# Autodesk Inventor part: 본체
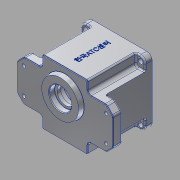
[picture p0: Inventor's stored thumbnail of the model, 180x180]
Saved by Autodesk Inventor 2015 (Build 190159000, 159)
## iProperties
Created: 2016-02
Part Number: 본체
Material: Aluminum 6061
Document SubType Name: Modeling
Designer: Administrator
Mass: 878.532 g
Surface Area: 762.372 cm^2
Volume: 325.382 cm^3
Density: 2.7 g/cm^3
Appearance: Aluminum - Flat
Author: Administrator
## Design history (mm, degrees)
sketch "Sketch1"
  geometry: L1 (70, 30)-(-70, 30); L2 (-70, 30)-(-70, -30); L3 (-70, -30)-(70, -30); L4 (70, -30)-(70, 30); L5 (70, 30)-(-70, -30); L6 (-70, 30)-(70, -30); 1 further point
  constraints: 12 end point, 2 midpoint, 2 parallel, 1 horizontal, 1 perpendicular
  dimensions: "d0" = 140 distance of L3.end L2.end; "d1" = 60 distance of L2.end L1.end
extrude "Extrusion1" new body sketch "Sketch1" distance "d2" = 13; taper "d3" = 0 deg
sketch "Sketch2"
  geometry: L1 (-47, 47)-(47, 47); L2 (47, 47)-(47, -47); L3 (47, -47)-(-47, -47); L4 (-47, -47)-(-47, 47); L5 (-47, 47)-(47, -47); L6 (47, 47)-(-47, -47); 1 further point
  constraints: 12 end point, 2 midpoint, 2 parallel, 1 horizontal, 1 perpendicular
  dimensions: "d4" = 94 distance of L2.end L3.end; "d5" = 94 distance of L1.end L2.end
extrude "Extrusion2" join sketch "Sketch2" distance "d6" = 80; taper "d7" = 0 deg
sketch "Sketch3"
  geometry: C1 r 43 at (0, 0); 1 further point
  constraints: 1 centre point, 1 coincident
  dimensions: "d8" = 86 diameter of C1
extrude "Extrusion3" cut sketch "Sketch3" distance "d9" = 9; taper "d10" = 0 deg
sketch "Sketch4"
  geometry: A1 r 40 centre (0, 0) between (-39.148, 8.214) and (-39.148, -8.214); A2 r 36 centre (0, 0) between (36, 0) and (-36, 0); A3 r 4 centre (36, 0) between (35.854, 3.997) and (35.852, -3.997); A4 r 4 centre (-36, 0) between (-35.852, -3.997) and (-35.852, 3.997); A5 r 3.5 centre (35.722, -7.495) between (39.148, -8.214) and (35.852, -3.997); A6 r 3.5 centre (-35.722, -7.495) between (-35.852, -3.997) and (-39.148, -8.214); A7 r 3.5 centre (-35.722, 7.495) between (-39.148, 8.214) and (-35.852, 3.997); A8 r 3.5 centre (35.722, 7.495) between (35.852, 3.997) and (39.148, 8.214); 1 further point
  constraints: 19 point on circle, 8 centre point, 8 tangent, 4 equal radius, 2 coincident, 2 horizontal alignment
  dimensions: "d11" = 80 diameter of A1; "d12" = 72 diameter of A2; "d13" = 4 radius of A3; "d14" = 3.5 radius of A5
extrude "Extrusion4" cut sketch "Sketch4" distance "d15" = 62; taper "d16" = 0 deg
sketch "Sketch5"
  geometry: C1 r 21 at (0, -11); C2 r 15 at (0, 20); 1 further point
  constraints: 2 centre point, 2 vertical alignment
  dimensions: "d17" = 42 diameter of C1; "d18" = 30 diameter of C2; "d19" = 11 distance of C1.centre point (0, 0); "d20" = 20 distance of point (0, 0) C2.centre
extrude "Extrusion5" join sketch "Sketch5" distance "d21" = 7; taper "d22" = 0 deg
hole "Hole1" diameter "d25" = 25; stored, may be unused: countersink angle "d29" = 90 deg, drill point angle "d31" = 0 deg; dims "d26" = 6, "d27" = 35, "d28" = 10, "d30" = 15, "d118" = 10, "d119" = 10
sketch "Sketch6"
  geometry: C1 r 28 at (0, 11); 1 further point
  constraints: 1 centre point, 1 vertical alignment
  dimensions: "d32" = 56 diameter of C1; "d33" = 11 distance of C1.centre point (0, 0)
extrude "Extrusion6" join sketch "Sketch6" distance "d34" = 7; taper "d35" = -10 deg
hole "Hole2" diameter "d38" = 25; stored, may be unused: countersink angle "d42" = 90 deg, drill point angle "d44" = 0 deg; dims "d36" = 10, "d37" = 10, "d39" = 6, "d40" = 32, "d41" = 8, "d43" = 13
hole "Hole3" diameter "d47" = 19; stored, may be unused: countersink angle "d51" = 90 deg, drill point angle "d53" = 0 deg; dims "d45" = 10, "d46" = 10, "d48" = 6, "d49" = 22, "d50" = 7, "d52" = 8
chamfer "Chamfer1" distance "d54" = 10; stored, may be unused: second distance "d55" = 2, angle "d56" = 45 deg
sketch "Sketch8"
  geometry: 3 further points
  constraints: 1 vertical alignment
  dimensions: "d57" = 38 distance of point (-60, -19) point (-60, 19); "d58" = 19 vertical distance of point (-60, -19) point (0, 0); "d59" = 60 horizontal distance of point (0, 0) point (-60, 19)
hole "Hole4" sketch "Sketch8" at (-60, 19), (-60, -19) diameter "d60" = 5; stored, may be unused: countersink angle "d64" = 90 deg, drill point angle "d66" = 0 deg; dims "d61" = 6, "d62" = 22, "d63" = 7, "d65" = 9
sketch "Sketch9"
  geometry: C1 r 2.5 at (-60, -19) reference; C2 r 2.5 at (-60, 19) reference; 1 further point
hole "Hole5" sketch "Sketch9" at (-60, -19), (-60, 19) diameter "d67" = 9; stored, may be unused: countersink angle "d71" = 90 deg, drill point angle "d73" = 0 deg; dims "d68" = 6, "d69" = 22, "d70" = 7, "d72" = 4
mirror "Mirror1"
sketch "Sketch10"
  geometry: L1 (-47, 47)-(47, 47) reference; L2 (47, 47)-(47, 30) reference; L3 (33, 47)-(47, 47); L4 (47, 47)-(47, 30); L5 (47, 30)-(33, 30); L6 (33, 30)-(33, 47); L7 (33, 47)-(47, 30); L8 (47, 47)-(33, 30); 2 further points
  constraints: 12 end point, 2 midpoint, 2 parallel, 1 horizontal, 1 perpendicular
  dimensions: "d74" = 14 distance of L4.end L5.end; "d75" = 17 distance of L1.end L4.end
extrude "Extrusion7" cut sketch "Sketch10" distance "d76" = 70; taper "d77" = 0 deg
mirror "Mirror2"
mirror "Mirror3"
fillet "Fillet1" dims "d78" = 8
sketch "Sketch12"
  geometry: 3 further points
  constraints: 1 horizontal alignment
  dimensions: "d79" = 40 horizontal distance of point (-33, 30) point (7, 70); "d80" = 80 distance of point (7, 70) point (-73, 70); "d81" = 40 horizontal distance of point (7, 70) point (-33, 30)
hole "Hole6" sketch "Sketch12" at (-73, 70), (7, 70) diameter "d82" = 7; stored, may be unused: countersink angle "d86" = 90 deg, drill point angle "d88" = 0 deg; dims "d83" = 6, "d84" = 22, "d85" = 7, "d87" = 4
mirror "Mirror4"
sketch "Sketch13"
  geometry: A1 r 4 centre (36, 0) between (35.852, 3.997) and (35.852, -3.997) reference; A2 r 4 centre (-36, 0) between (-35.852, -3.997) and (-35.852, 3.997) reference; 1 further point
hole "Hole7" sketch "Sketch13" at (36, 0), (-36, 0) diameter "d89" = 3.242; stored, may be unused: countersink angle "d93" = 90 deg, drill point angle "d95" = 118 deg; dims "d90" = 7, "d91" = 22, "d92" = 7, "d94" = 9
fillet "Fillet2" dims "d97" = 5
sketch "Sketch16" dims "d9" = 9, "d10" = 0
  geometry: L1 (-66, 0)-(0, 0) reference; L2 (-72, 80)-(6, 80) reference; 3 further points
  constraints: 1 midpoint, 1 vertical alignment, 1 other
  dimensions: "d98" = 40 distance from line of L2 point (-33, 40)
emboss "Emboss1" sketch "Sketch16" dims "d9" = 9, "d10" = 0, "d99" = 0.5, "d100" = 0
chamfer "Chamfer2" distance "d101" = 1; stored, may be unused: second distance "d102" = 2, angle "d103" = 45 deg
fillet "Fillet3" dims "d104" = 0.3
fillet "Fillet4" dims "d105" = 5
fillet "Fillet6" dims "d107" = 3
fillet "Fillet7" dims "d108" = 2
fillet "Fillet8" dims "d109" = 2
fillet "Fillet9" dims "d110" = 2
sketch "Sketch17"
  geometry: L1 (-33, 47)-(-33, 35) reference; L2 (-57.929, 30)-(-38, 30) reference; L3 (-68.536, 21.464)-(-61.464, 28.536) reference; L4 (-70, -17.929)-(-70, 17.929) reference; L5 (-61.464, -28.536)-(-68.536, -21.464) reference; L6 (-38, -30)-(-57.929, -30) reference; L7 (-33, -35)-(-33, -47) reference; L8 (33, -47)-(-33, -47) reference; L9 (33, -47)-(33, -35) reference; L10 (57.929, -30)-(38, -30) reference; L11 (68.536, -21.464)-(61.464, -28.536) reference; L12 (70, 17.929)-(70, -17.929) reference; L13 (61.464, 28.536)-(68.536, 21.464) reference; L14 (38, 30)-(57.929, 30) reference; L15 (33, 35)-(33, 47) reference; L16 (-33, 47)-(33, 47) reference; L17 (32, 45)-(32, 35); L18 (38, 29)-(57.929, 29); L19 (60.757, 27.828)-(67.828, 20.757); L20 (69, 17.929)-(69, -17.929); L21 (67.828, -20.757)-(60.757, -27.828); L22 (57.929, -29)-(38, -29); L23 (32, -35)-(32, -45); L24 (31, -46)-(-31, -46); L25 (-32, -45)-(-32, -35); L26 (-38, -29)-(-57.929, -29); L27 (-60.757, -27.828)-(-67.828, -20.757); L28 (-69, -17.929)-(-69, 17.929); L29 (-67.828, 20.757)-(-60.757, 27.828); L30 (-57.929, 29)-(-38, 29); L31 (-32, 35)-(-32, 45); L32 (-31, 46)-(31, 46); C1 r 2.5 at (-60, -19) reference; C2 r 2.5 at (-60, 19) reference; C3 r 2.5 at (60, 19) reference; C4 r 2.5 at (60, -19) reference; A1 r 5 centre (-38, 35) between (-38, 30) and (-33, 35) reference; A2 r 5 centre (-57.929, 25) between (-57.929, 30) and (-61.464, 28.536) reference; A3 r 5 centre (-65, 17.929) between (-68.536, 21.464) and (-70, 17.929) reference; A4 r 5 centre (-65, -17.929) between (-70, -17.929) and (-68.536, -21.464) reference; A5 r 5 centre (-57.929, -25) between (-61.464, -28.536) and (-57.929, -30) reference; A6 r 5 centre (-38, -35) between (-33, -35) and (-38, -30) reference; A7 r 5 centre (38, -35) between (38, -30) and (33, -35) reference; A8 r 5 centre (57.929, -25) between (57.929, -30) and (61.464, -28.536) reference; A9 r 5 centre (65, -17.929) between (68.536, -21.464) and (70, -17.929) reference; A10 r 5 centre (65, 17.929) between (70, 17.929) and (68.536, 21.464) reference; A11 r 5 centre (57.929, 25) between (61.464, 28.536) and (57.929, 30) reference; A12 r 5 centre (38, 35) between (33, 35) and (38, 30) reference; A13 r 1 centre (31, 45) between (32, 45) and (31, 46); A14 r 6 centre (38, 35) between (32, 35) and (38, 29); A15 r 4 centre (57.929, 25) between (60.757, 27.828) and (57.929, 29); A16 r 4 centre (65, 17.929) between (69, 17.929) and (67.828, 20.757); A17 r 4 centre (65, -17.929) between (67.828, -20.757) and (69, -17.929); A18 r 4 centre (57.929, -25) between (57.929, -29) and (60.757, -27.828); A19 r 6 centre (38, -35) between (38, -29) and (32, -35); A20 r 1 centre (31, -45) between (31, -46) and (32, -45); A21 r 1 centre (-31, -45) between (-32, -45) and (-31, -46); A22 r 6 centre (-38, -35) between (-32, -35) and (-38, -29); A23 r 4 centre (-57.929, -25) between (-60.757, -27.828) and (-57.929, -29); A24 r 4 centre (-65, -17.929) between (-69, -17.929) and (-67.828, -20.757); A25 r 4 centre (-65, 17.929) between (-67.828, 20.757) and (-69, 17.929); A26 r 4 centre (-57.929, 25) between (-57.929, 29) and (-60.757, 27.828); A27 r 6 centre (-38, 35) between (-38, 29) and (-32, 35); A28 r 1 centre (-31, 45) between (-31, 46) and (-32, 45); 1 further point
  constraints: 32 end point, 32 point on circle, 16 centre point, 24 other
  dimensions: "d111" = 1 distance between parallel lines of L16 L32
extrude "Extrusion8" cut sketch "Sketch17" distance "d112" = 1; taper "d113" = 0 deg
fillet "Fillet10" dims "d114" = 2
fillet "Fillet11" dims "d115" = 0.3
fillet "Fillet12" dims "d116" = 2
fillet "Fillet13" dims "d117" = 2
body "Solid1"
node "Projected Loop2"
